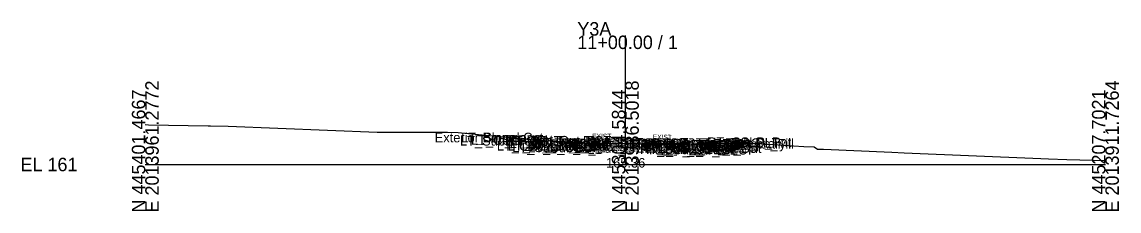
# Model space of a CAD drawing. Extents: x -26 to 205, y -10 to 5029.
# Drawn here: x -25.7 to 202.8, y 1990.3 to 2029.7 of the extents above; entities that cross this region are included whole.
import ezdxf

# ---------------------------------------------------------------- set-up
doc = ezdxf.new("R2010")
doc.units = 0
for name, color, linetype in [('Default', 7, 'Continuous'), ('Exist Cross Section Cell', 7, 'Continuous'), ('Exist XS Center Line Elevation Label', 7, 'Continuous'), ('Exist XS Ground Line', 7, 'Continuous'), ('Prop XS SE Text', 7, 'Continuous'), ('Scratch_Level_0', 7, 'Continuous')]:
    doc.layers.add(name, color=color, linetype=linetype)

msp = doc.modelspace()

# ---------------------------------------------------------------- linework, layer by layer
at = {"layer": 'Exist Cross Section Cell'}
for p, q in [((100, 2000), (100, 2026.84)), ((0, 2000), (100, 2000)), ((100, 2000), (200, 2000))]:
    msp.add_line(p, q, dxfattribs=at)
at = {"layer": 'Exist XS Ground Line'}
msp.add_lwpolyline([(0, 2008.34), (0.7, 2008.27), (13.1, 2008.05), (13.57, 2008.06), (17.23, 2007.98), (48.29, 2006.72), (48.99, 2006.71), (51.42, 2006.75), (51.85, 2006.75), (56.38, 2006.76), (57.32, 2006.76), (59.43, 2006.76), (59.78, 2006.76), (60.57, 2006.76), (60.97, 2006.76), (61.43, 2006.76), (62.93, 2006.72), (65.17, 2006.65), (68.72, 2006.31), (75.14, 2005.68), (77.39, 2005.51), (78.86, 2005.32), (80.21, 2005.18), (85.32, 2004.89), (89.68, 2004.6), (90.95, 2004.48), (91.37, 2004.43), (94.29, 2004.41), (100, 2004.36), (102.78, 2004.34), (107.82, 2004.22), (114.91, 2004.07), (115.78, 2004.07), (116.29, 2004.07), (116.88, 2004.51), (118.96, 2004.45), (121.57, 2004.43), (124.48, 2004.4), (126.4, 2004.41), (137.16, 2003.77), (139.31, 2003.66), (140.05, 2003.22), (141.24, 2003.17), (155.49, 2002.59), (158.1, 2002.4), (186.52, 2001.22), (188.15, 2001.16), (191.94, 2001.05), (200, 2000.81)], dxfattribs=at)

# ---------------------------------------------------------------- texts
at = {"layer": 'Default'}
msp.add_text('-', height=0.0001, dxfattribs=at).set_placement((0, 2000))
at = {"layer": 'Exist Cross Section Cell'}
for s, p in [('Y3A', (90, 2026.84)), ('11+00.00 / 1', (90, 2024.04)), ('EL 161', (-26, 1998.6))]:
    msp.add_text(s, height=2.8, dxfattribs=at).set_placement(p)
for s, p in [('E 2013961.2772', (2.8, 1990)), ('E 2013936.5018', (102.8, 1990)), ('E 2013911.7264', (202.8, 1990)), ('N 445401.4667', (0, 1990)), ('N 445304.5844', (100, 1990)), ('N 445207.7021', (200, 1990))]:
    msp.add_text(s, height=2.8, rotation=90, dxfattribs=at).set_placement(p)
at = {"layer": 'Exist XS Center Line Elevation Label'}
msp.add_text('165.36', height=2, dxfattribs=at).set_placement((95.97, 1999.36))
at = {"layer": 'Prop XS SE Text'}
for rotation, p in [(359.4271, (93.08, 2005.43)), (358.8542, (105.7, 2005.25))]:
    msp.add_text('EXIST.', height=1, rotation=rotation, dxfattribs=at).set_placement(p)
at = {"layer": 'Scratch_Level_0'}
for s, p in [('Exterior Boundary', (60.29, 2004.61)), ('LT_Slope_Cut', (65.79, 2004.61)), ('LT_Sub_Trench_Out_DLT', (65.55, 2003.95)), ('LT_CSLP_Pnt', (67.85, 2004.1)), ('LT_CG1_Shelf_Out', (73.23, 2002.91)), ('LT_CG_Top_Face', (74.94, 2003.91)), ('LT_CG_Top_BOC', (75.46, 2003.91)), ('LT_CG_Bot_BOC', (75.49, 2002.91)), ('LT_CG_Top_Gut', (75.91, 2003.41)), ('LT_Sub_OEOP', (76.46, 2002.58)), ('LT_CG_Bot_IE', (79.59, 2002.88)), ('LT_Sub_OEOT', (79.76, 2002.55)), ('LT_PV2_OEOT', (79.85, 2003.22)), ('LT_PV3_OEOT', (79.85, 2002.88)), ('LT_PV1_OEOT', (80.42, 2003.47)), ('RT_PV_IEEOP_EG', (88.14, 2003.36)), ('LT_Sub_OEEOP', (89.21, 2002.45)), ('LT_PV2_OEEOP', (89.31, 2003.11)), ('LT_PV3_OEEOP', (89.31, 2002.78)), ('LT_PV1_OEEOP', (89.87, 2003.24)), ('RT_PV2_IEEOP', (89.91, 2003.11)), ('RT_PV3_IEEOP', (89.91, 2002.78)), ('LT_PV2_IEEOP', (89.95, 2003.11)), ('RT_PV1_IEEOP', (90.47, 2003.24)), ('LT_PV1_IEEOP', (90.52, 2003.24)), ('PV2_PGL', (93.91, 2003.11)), ('PV1_PGL', (94.47, 2003.36)), ('RT_PV_Sub_Tie_Out', (98.79, 2003.09)), ('RT_Sub_Trench_Out_DLT', (100.18, 2003.49)), ('RT_PV_OEEOP_EG', (101.4, 2003.09)), ('RT_Sub_OEEOP', (103.07, 2002.17)), ('RT_PV2_OEEOP', (103.17, 2002.84)), ('RT_PV3_OEEOP', (103.17, 2002.5)), ('RT_PV1_OEEOP', (103.73, 2002.96)), ('RT_CG_Top_Face', (104.12, 2003.45)), ('RT_CG1_Shelf_Out', (104.41, 2002.42)), ('RT_CG_Bot_IE', (104.77, 2002.48)), ('RT_Sub_OEOT', (104.94, 2002.15)), ('RT_PV2_OEOT', (105.03, 2002.82)), ('RT_PV3_OEOT', (105.03, 2002.48)), ('RT_CG_Top_Gut', (105.1, 2002.95)), ('RT_PV1_OEOT', (105.6, 2003.07)), ('RT_CG_Top_BOC', (105.65, 2003.45)), ('RT_CG_Bot_BOC', (105.68, 2002.43)), ('Exterior Boundary', (111.99, 2003.32)), ('RT_CSLP_Pnt', (117.03, 2003.64)), ('RT_Slope_Fill', (118.32, 2003.32)), ('RT_Sub_OEOP', (108.31, 2002.08))]:
    msp.add_text(s, height=2, dxfattribs=at).set_placement(p)

doc.saveas('drawing.dxf')
